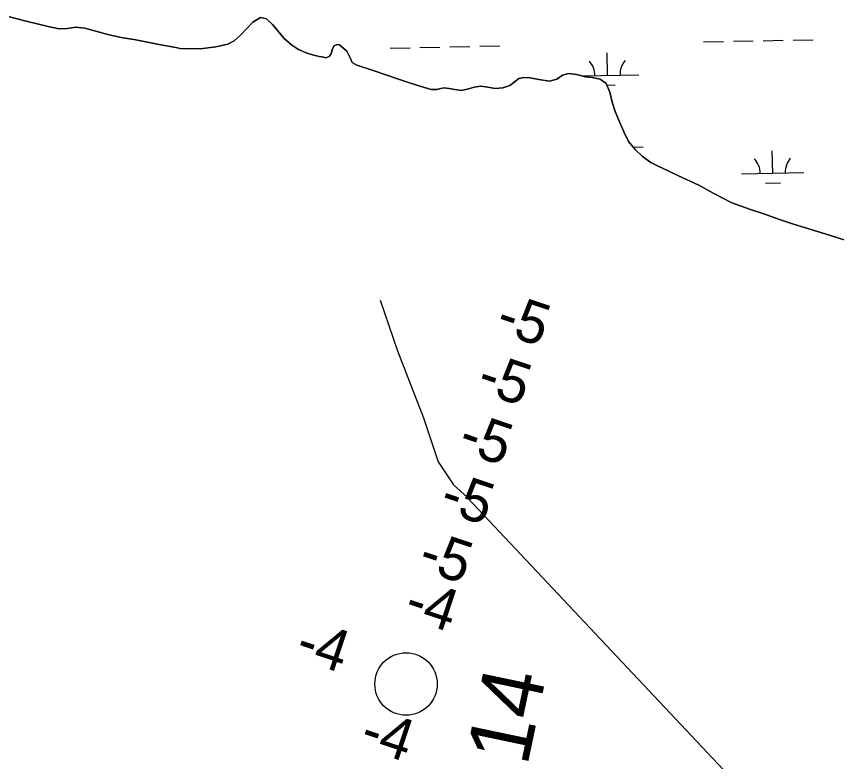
# Model space of a CAD drawing. Extents: x 3989314 to 4027622, y 243956 to 270014.
# Drawn here: x 4015668 to 4016981, y 256366 to 257560 of the extents above; entities that cross this region are included whole.
import ezdxf

# ---------------------------------------------------------------- set-up
doc = ezdxf.new("R2010")
doc.units = 0
for name, color, linetype in [('V-RIVR-EDGE', 7, 'Continuous'), ('V-RIVR-IDEN', 7, 'Continuous'), ('V-RIVR-MILE', 7, 'Continuous'), ('V-RIVR-RANG', 7, 'Continuous'), ('V-TOPO-MINR', 7, 'Continuous'), ('V-WETL-SWMP', 7, 'Continuous')]:
    doc.layers.add(name, color=color, linetype=linetype)

msp = doc.modelspace()

# ---------------------------------------------------------------- linework, layer by layer
at = {"layer": 'V-RIVR-EDGE'}
msp.add_lwpolyline([(4015654.6, 257559.6), (4015683.3, 257552), (4015720.5, 257542.9), (4015736.2, 257539.5), (4015749.1, 257540.1), (4015762.8, 257542.6), (4015777.3, 257540.8), (4015814, 257530.4), (4015835.6, 257525.7), (4015859, 257521.9), (4015896.3, 257514.5), (4015925.6, 257509.3), (4015929.2, 257508.4), (4015962.2, 257507.8), (4015987.2, 257511.1), (4016006.1, 257515), (4016016.6, 257520.5), (4016027.2, 257530.3), (4016036, 257539.9), (4016046.3, 257550.5), (4016058.4, 257557.8), (4016068.3, 257555.9), (4016077.6, 257546.7), (4016086.1, 257536.3), (4016096.2, 257524.9), (4016108, 257513.8), (4016119.2, 257506.6), (4016131.8, 257501.4), (4016142.1, 257498.2), (4016152.8, 257495.3), (4016157.5, 257495), (4016163.1, 257493.4), (4016168.7, 257495.5), (4016171.6, 257499.8), (4016173.2, 257506.7), (4016176.3, 257512.2), (4016181.2, 257514.7), (4016185.1, 257514.2), (4016196.6, 257503.7), (4016202.5, 257492.2), (4016205.5, 257485.7), (4016212.8, 257481.4), (4016239.2, 257473.1), (4016279.7, 257459.1), (4016297.1, 257453.4), (4016310.5, 257448.7), (4016331.7, 257442.7), (4016341.2, 257442.3), (4016347.6, 257444.3), (4016352.2, 257445.2), (4016360.6, 257444.3), (4016369.9, 257442.3), (4016380, 257440.8), (4016390.2, 257443), (4016400.5, 257446.1), (4016411.3, 257448), (4016422.6, 257446.5), (4016434.5, 257444.2), (4016446.7, 257445), (4016457.7, 257448.9), (4016466.9, 257455.7), (4016472.4, 257460.3), (4016480.2, 257461.7), (4016490.3, 257461.4), (4016504.2, 257458.3), (4016521.5, 257455.6), (4016533.3, 257459.3), (4016542.4, 257465.6), (4016552.1, 257468.3), (4016564.6, 257466.6), (4016578.8, 257463), (4016589.5, 257461.6), (4016602.4, 257458.8), (4016612.4, 257452), (4016617.8, 257438.3), (4016621.8, 257422.4), (4016626.6, 257407.2), (4016633.5, 257390.5), (4016640.4, 257374.7), (4016647.8, 257359.4), (4016658.4, 257346.4), (4016670.3, 257335.3), (4016683.5, 257325.6), (4016697.5, 257318.6), (4016701.4, 257317.1), (4016727.8, 257304.3), (4016760.7, 257289.3), (4016784.4, 257276.1), (4016813.3, 257261), (4016843.3, 257250.2), (4016864.4, 257243.5), (4016889.9, 257234.2), (4016910.4, 257227.3), (4016931.2, 257220.8), (4016969.7, 257209.2), (4016997.9, 257200.1)], dxfattribs=at)
at = {"layer": 'V-RIVR-MILE'}
msp.add_circle((4016291.7, 256490.3), 50, dxfattribs=at)
at = {"layer": 'V-TOPO-MINR'}
msp.add_lwpolyline([(4016250.1, 257105), (4016278, 257023.9), (4016319.6, 256916.5), (4016342.9, 256846.4), (4016367.9, 256809.3), (4016389.8, 256789.6), (4016389.8, 256789.5), (4016389.7, 256789.3), (4016389.7, 256789.1), (4016389.9, 256788.7), (4016390, 256788.6), (4017432.6, 255680.8)], dxfattribs=at)
at = {"layer": 'V-WETL-SWMP'}
for p, q in [((4016767.8, 257518.8), (4016799.8, 257519.5)), ((4016815.8, 257519.8), (4016847.8, 257520.4)), ((4016863.8, 257520.7), (4016895.8, 257521.4)), ((4016911.8, 257521.7), (4016943.8, 257522.3)), ((4016266, 257508.8), (4016298, 257509.5)), ((4016314, 257509.8), (4016346, 257510.4)), ((4016362, 257510.7), (4016394, 257511.4)), ((4016410, 257511.7), (4016442, 257512.3)), ((4016614.3, 257465), (4016613.6, 257501)), ((4016574.2, 257464.2), (4016664.3, 257466)), ((4016613.4, 257449.5), (4016626.6, 257449.8)), ((4016655.1, 257350.4), (4016671.2, 257350.7)), ((4016878.9, 257308.4), (4016878.2, 257344.4)), ((4016828.9, 257307.4), (4016928.9, 257309.4)), ((4016867.2, 257292.7), (4016891.2, 257293.2))]:
    msp.add_line(p, q, dxfattribs=at)
for points in [[(4016640.4, 257374.7), (4016633.5, 257390.5), (4016626.6, 257407.2), (4016621.8, 257422.4), (4016617.8, 257438.3), (4016612.4, 257452), (4016602.4, 257458.8), (4016589.6, 257461.6), (4016578.8, 257463), (4016564.6, 257466.6), (4016552.1, 257468.3), (4016542.4, 257465.6), (4016533.3, 257459.3), (4016521.5, 257455.6), (4016504.2, 257458.3), (4016490.3, 257461.4), (4016480.2, 257461.7), (4016472.4, 257460.3), (4016466.9, 257455.7), (4016457.7, 257448.9), (4016446.7, 257445), (4016434.5, 257444.2), (4016422.6, 257446.5), (4016411.3, 257448), (4016400.5, 257446.1), (4016390.2, 257443), (4016380, 257440.8), (4016369.9, 257442.3), (4016360.6, 257444.3), (4016352.2, 257445.2), (4016347.6, 257444.3), (4016341.2, 257442.3), (4016331.7, 257442.7), (4016310.5, 257448.7), (4016297.1, 257453.4), (4016279.7, 257459.1), (4016239.2, 257473.1), (4016212.8, 257481.4), (4016205.5, 257485.7), (4016202.5, 257492.2), (4016196.6, 257503.7), (4016185.1, 257514.2), (4016181.2, 257514.7), (4016176.3, 257512.2), (4016173.2, 257506.7), (4016171.6, 257499.8), (4016168.7, 257495.5), (4016163.1, 257493.4), (4016157.5, 257495), (4016152.8, 257495.3), (4016142.1, 257498.2), (4016131.8, 257501.4), (4016119.2, 257506.6), (4016108, 257513.8), (4016096.2, 257524.9), (4016086.1, 257536.3), (4016077.6, 257546.7), (4016068.3, 257555.9), (4016058.4, 257557.8), (4016046.3, 257550.5), (4016036, 257539.9), (4016027.2, 257530.3), (4016016.6, 257520.5), (4016006.1, 257515), (4015987.2, 257511.1), (4015962.2, 257507.8), (4015929.2, 257508.4), (4015925.6, 257509.3), (4015896.3, 257514.5), (4015859, 257521.9), (4015835.6, 257525.7), (4015814, 257530.4), (4015777.3, 257540.8), (4015762.8, 257542.6), (4015749.2, 257540.1), (4015736.2, 257539.5), (4015720.5, 257542.9), (4015683.3, 257552), (4015654.6, 257559.6)], [(4016998, 257200.1), (4016969.7, 257209.2), (4016931.2, 257220.8), (4016910.4, 257227.3), (4016889.9, 257234.2), (4016864.4, 257243.5), (4016843.3, 257250.2), (4016813.3, 257261), (4016784.4, 257276.1), (4016760.7, 257289.3), (4016727.8, 257304.3), (4016701.4, 257317.1), (4016697.5, 257318.6), (4016683.5, 257325.6), (4016670.3, 257335.3), (4016658.4, 257346.4), (4016647.8, 257359.4), (4016640.4, 257374.7)]]:
    msp.add_lwpolyline(points, dxfattribs=at)
for centre, start, end in [((4016559, 257464.4), 0.3699, 41.9135), ((4016669.5, 257466.6), 140.3699, 181.9135), ((4016823.6, 257307.8), 0.3699, 41.9135), ((4016934.1, 257310), 140.3699, 181.9135)]:
    msp.add_arc(centre, 35.2, start, end, dxfattribs=at)

# ---------------------------------------------------------------- texts
at = {"layer": 'V-RIVR-IDEN'}
msp.add_text('14', height=100, rotation=78.1474, dxfattribs=at).set_placement((4016485.6, 256357.2))
at = {"layer": 'V-RIVR-RANG'}
for s, p in [('-5', (4016432.4, 257055.4)), ('-5', (4016402.2, 256960.1)), ('-5', (4016372.4, 256864.6)), ('-5', (4016342.7, 256769.2)), ('-5', (4016308.2, 256675.3)), ('-4', (4016285.6, 256598.4)), ('-4', (4016111.4, 256532.9)), ('-4', (4016214.7, 256390.4))]:
    msp.add_text(s, height=67, rotation=341.535, dxfattribs=at).set_placement(p)

doc.saveas('drawing.dxf')
